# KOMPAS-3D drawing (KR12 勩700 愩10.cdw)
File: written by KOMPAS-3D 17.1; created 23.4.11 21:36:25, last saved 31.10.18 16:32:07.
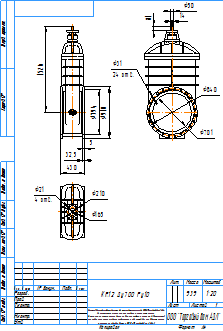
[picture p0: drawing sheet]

Sheet 1: A4, portrait

Title block, sheet 1: name: KR12 Ду700 Ру10; mass: 939; sheets: 1; sheet format: A4; stored path: \\adlc.lan\data\АДЛ_ПКД\3D-модели\ADL production\Клиновые задвижки серии KR ГРАНАР\Клиновые задвижки KR12\KOMPAS 2D\KR12 Ду700 Ру10.cdw

Views: Спереди 4, Проекционный вид 5
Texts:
  Рама для чертежей
  Лит-Масса-Масштаб
  Материал-Предприятие
  Масштаб
  Изм.
  Лист
  № докум.
  Подп.
  Дата
  Лит.
  Разраб.
  Пров.
  Т.контр.
  Листов
  Внимание! Данный продукт является объектом авторского права ООО «Торговый Дом АДЛ».
  Запрещается изменение, копирование, распространение
  (в том числе путем копирования на другие сайты и ресурсы в Интернете)
  или любое иное использование информации и объектов без предварительного
  согласия правообладателя (ООО «Торговый Дом АДЛ»).
  Н.контр.
  Утв.
  ООО "Торговый дом АДЛ"
  Изменение
  Номер документа
  Подпись
  Обозначение документа
  Наименование изделия
  Масса изделия по ГОСТ 2.109-73
  Порядковый номер листа
  Общее количество листов в документе
  Характер работы, выполненной лицом, подписавшим документ
  Наименование или индекс предприятия, выпускающего документ
  Инв. № подл.
  Подп. и дата
  Взам. инв. №
  Инв. № дубл.
  Инвентарный номер подлинника по ГОСТ 2.501-68
  Подпись принявшего подлинник в отдел технической документации
  Инвентарный номер подлинника, взамен которого выпущен данный подлинник
  Инвентарный номер дубликата по ГОСТ 2.502-68
  Подпись принявшего дубликат в отдел технической документации
  Справ. №
  Перв. примен.
  Обозначение документа, взамен или на основании которого выпущен данный документ
  Обозначение документа, в котором впервые записан данный документ
  Подпись лица, копировавшего чертеж
  Обозначение формата листа
  !Рама для чертежа
Dimensions and other numbers on the sheet: 910; 794; 1526; 430; 32,5; 5; 21; 4 отв.; 210; 165; 1:20; 1; 939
